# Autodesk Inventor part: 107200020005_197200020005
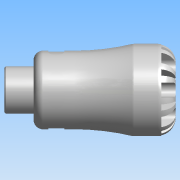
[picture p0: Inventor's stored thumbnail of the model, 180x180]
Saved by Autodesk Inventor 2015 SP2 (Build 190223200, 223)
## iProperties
Created: 2016-12
Part Number: 107200020005_197200020005
Material: PVC-Piping
Description: PLASSON MALE INTEGRAL BRASS THREAD 20X1/2" SERIES 1
Document SubType Name: Modeling
Designer: KIM
Mass: 61.7504 g
Surface Area: 140.097 cm^2
Volume: 44.1074 cm^3
Density: 1.4 g/cm^3
Appearance: Smooth - White
Author: KIM
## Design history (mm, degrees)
derived "1072.ipt"
feature "Solid1::1072.ipt"
tag "TaggingFeature1"
body "Solid1"
other parameters: "d0" = 76, "d1" = 18.9, "d3" = 25, "d4" = 41, "d6" = 45, "d8" = 34.85, "d13" = 6.4, "d14" = 6.4, "d15" = 0, "d17" = 360 deg, "d19" = 8 deg, "d20" = 0.4, "d21" = 0.4, "d22" = 8 deg, "d24" = 0, "d26" = 360 deg, "d32" = 4.1, "d33" = 4.1, "d34" = 20.955, "d38" = 13, "d39" = 0.62865, "d42" = 7, "d43" = 4.6, "d45" = 12.544, "d46" = 0, "d59" = 360 deg, "d61" = 5.95, "d62" = 0.4, "d64" = 0, "d65" = 0.41, "d68" = 2.85714, "E_" = 41, "H_" = 76, "l_" = 45, "R_" = 20.955, "l_2" = 13, "d9" = 8, "d11" = 41, "d12" = 25
